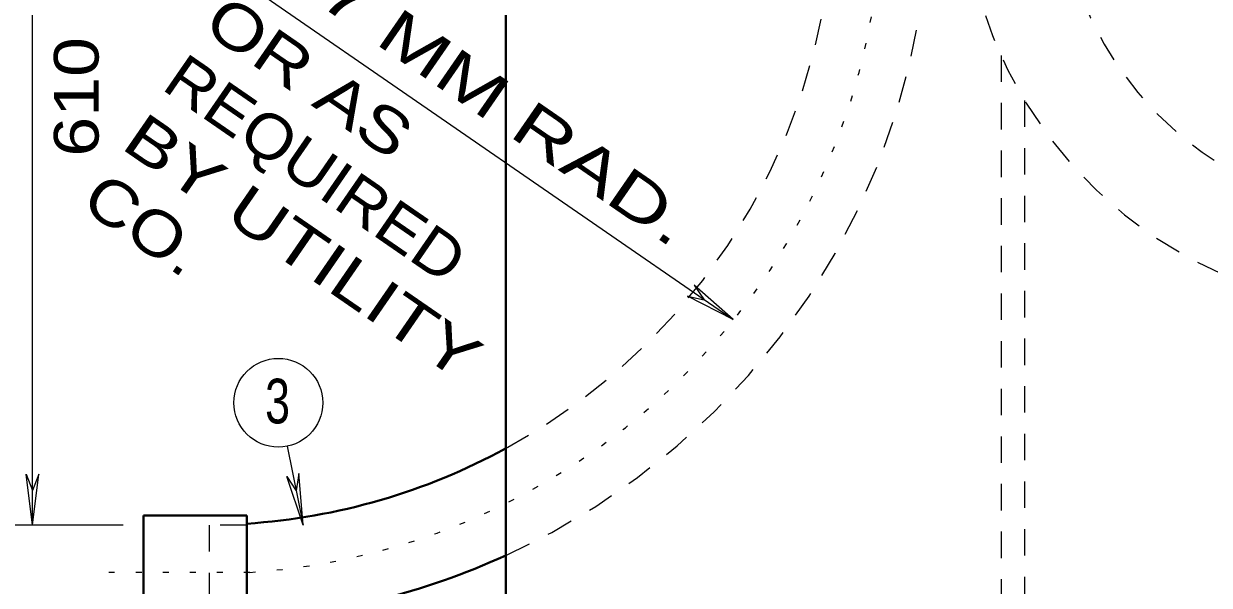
# Model space of a CAD drawing. Extents: x 312583 to 312854, y 144419 to 144597.
# Drawn here: x 312713.43 to 312733.6, y 144526.9 to 144536.45 of the extents above; entities that cross this region are included whole.
import ezdxf

# ---------------------------------------------------------------- set-up
doc = ezdxf.new("R2010")
doc.units = 0
doc.header["$LTSCALE"] = 0.3
doc.linetypes.add('DOTTED', pattern=[1.5, 0.3, -1.2])
doc.linetypes.add('SHORT_DASHED', pattern=[2.7, 1.5, -1.2])
doc.layers.add('1', color=7, linetype='Continuous', lineweight=25)
doc.layers.add('2', color=7, linetype='Continuous', lineweight=13)

msp = doc.modelspace()

# ---------------------------------------------------------------- linework, layer by layer
at = {"layer": '1', "lineweight": 40}
for p, q in [((312721.6325, 144544.3469), (312721.6325, 144521.9833)), ((312717.2241, 144528.0859), (312715.4685, 144528.0859)), ((312715.4685, 144528.0859), (312715.4685, 144526.1386)), ((312717.2241, 144528.0859), (312717.2241, 144526.1386))]:
    msp.add_line(p, q, dxfattribs=at)
at = {"layer": '1', "linetype": 'SHORT_DASHED'}
for p, q in [((312730.0581, 144535.9136), (312730.0581, 144521.9833)), ((312730.4568, 144535.1469), (312730.4568, 144521.9833)), ((312716.5878, 144527.9249), (312716.5878, 144526.2996)), ((312717.2241, 144527.9249), (312716.5878, 144527.9249))]:
    msp.add_line(p, q, dxfattribs=at)
at = {"layer": '1', "linetype": 'DOTTED', "lineweight": 13}
msp.add_line((312717.2778, 144527.1199), (312714.5638, 144527.1199), dxfattribs=at)
at = {"layer": '1', "linetype": 'SHORT_DASHED'}
for centre, radius, start, end in [((312716.5182, 144538.6104), 10.6854, 298.57546, 1.79804), ((312736.8038, 144538.9545), 5.75, 184.14986, 265.21724), ((312716.5182, 144538.6104), 12.3146, 294.52268, 358.54105), ((312736.7767, 144538.9543), 7.3792, 186.13, 266.47596)]:
    msp.add_arc(centre, radius, start, end, dxfattribs=at)
at = {"layer": '1', "linetype": 'DOTTED', "lineweight": 13}
msp.add_arc((312716.5182, 144538.6104), 11.516, 273.77656, 358.54081, dxfattribs=at)
at = {"layer": '1', "lineweight": 40}
for radius, start, end in [(10.6854, 273.78479, 298.57546), (12.3146, 273.28349, 294.52268)]:
    msp.add_arc((312716.5182, 144538.6104), radius, start, end, dxfattribs=at)
at = {"layer": '2'}
for p, q in [((312714.6328, 144538.9189), (312725.4965, 144531.4209)), ((312724.8371, 144532.0036), (312725.0058, 144531.7583)), ((312725.4965, 144531.4209), (312724.8371, 144532.0036)), ((312724.7221, 144531.8196), (312725.0058, 144531.7583)), ((312725.4965, 144531.4209), (312724.7221, 144531.8196)), ((312717.9141, 144529.2666), (312718.1825, 144527.9249)), ((312713.4751, 144528.7913), (312713.5825, 144528.5153)), ((312713.5825, 144527.9249), (312713.4751, 144528.7913)), ((312713.6898, 144528.7913), (312713.5825, 144528.5153)), ((312713.5825, 144527.9249), (312713.6898, 144528.7913)), ((312717.9065, 144528.7529), (312718.0675, 144528.5076)), ((312718.1825, 144527.9249), (312717.9065, 144528.7529)), ((312718.1135, 144528.7989), (312718.0675, 144528.5076)), ((312718.1825, 144527.9249), (312718.1135, 144528.7989)), ((312715.1235, 144527.9249), (312713.0458, 144527.9249))]:
    msp.add_line(p, q, dxfattribs=at)
msp.add_lwpolyline([(312713.5825, 144527.9249), (312713.5825, 144543.0666), (312713.5825, 144544.9833)], dxfattribs=at)
at = {"layer": '2', "lineweight": 25}
msp.add_circle((312717.7614, 144530.0045), 0.7557, dxfattribs=at)

# ---------------------------------------------------------------- texts
at = {"layer": '2'}
for s, rotation, width, p in [('457 MM RAD.   ', 325.387, 1.4, (312717.1088, 144537.6996)), ('OR AS', 325.4, 1.25, (312716.4475, 144536.3537)), ('610 ', 90, 1.2, (312714.7045, 144534.1902)), ('REQUIRED', 325.4, 1.1, (312715.7547, 144535.3494)), ('BY UTILITY', 325.4, 1.3, (312715.0619, 144534.3452)), ('CO.', 325.4, 1.2, (312714.3691, 144533.341))]:
    msp.add_text(s, height=0.76, rotation=rotation, dxfattribs=dict(at, width=width)).set_placement(p)
at = {"layer": '2', "width": 0.75}
msp.add_text('3', height=0.76, dxfattribs=at).set_placement((312717.5368, 144529.6539))

doc.saveas('drawing.dxf')
